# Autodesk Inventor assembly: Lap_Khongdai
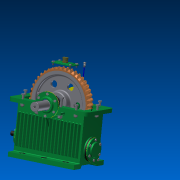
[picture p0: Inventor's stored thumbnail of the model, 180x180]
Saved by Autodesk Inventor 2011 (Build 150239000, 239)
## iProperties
Created: 2011-05
Part Number: Lap_Khongdai
Document SubType Name: Assembly
Designer: 904Chiaki
Author: 904Chiaki
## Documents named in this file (39)
- E:\2.FINISH\DOAN_CTM_final\Lap_Khongdai.iam
- E:\2.FINISH\DOAN_CTM_final\Thanhop.ipt
- E:\2.FINISH\DOAN_CTM_final\Bearing2_1.ipt
- E:\2.FINISH\DOAN_CTM_final\Bearing2_2.ipt
- E:\2.FINISH\DOAN_CTM_final\Bearing3.ipt
- E:\2.FINISH\DOAN_CTM_final\Naphop.ipt
- E:\2.FINISH\DOAN_CTM_final\Napquansat.ipt
- E:\2.FINISH\DOAN_CTM_final\Nutthonghoi.iam
- E:\2.FINISH\DOAN_CTM_final\Chotdinhvi.ipt
- E:\2.FINISH\DOAN_CTM_final\Bulongbich.ipt
- E:\2.FINISH\DOAN_CTM_final\Daiocbich.ipt
- E:\2.FINISH\DOAN_CTM_final\Vongdembich.ipt
- E:\2.FINISH\DOAN_CTM_final\BulongCanhO.ipt
- E:\2.FINISH\DOAN_CTM_final\Daioccanho.ipt
- E:\2.FINISH\DOAN_CTM_final\VongdemcanhO.ipt
- E:\2.FINISH\DOAN_CTM_final\Vitghepnapcuatham.ipt
- E:\2.FINISH\DOAN_CTM_final\VongChandau2.ipt
- E:\2.FINISH\DOAN_CTM_final\Shaft3.ipt
- E:\2.FINISH\DOAN_CTM_final\Onglot.ipt
- E:\2.FINISH\DOAN_CTM_final\VongChandau1.ipt
- E:\2.FINISH\DOAN_CTM_final\Lap1_codai\Design Accelerator\Key Connection2.iam
- E:\2.FINISH\DOAN_CTM_final\Lap1_codai\Design Accelerator\Key Connection3.iam
- E:\2.FINISH\DOAN_CTM_final\Trucvit.iam
- E:\2.FINISH\DOAN_CTM_final\Coclot1.ipt
- E:\2.FINISH\DOAN_CTM_final\Coclot2.ipt
- E:\2.FINISH\DOAN_CTM_final\NapO2.ipt
- E:\2.FINISH\DOAN_CTM_final\NapO2_2.ipt
- E:\2.FINISH\DOAN_CTM_final\Vongphot2.ipt
- E:\2.FINISH\DOAN_CTM_final\VongdemnapO2.ipt
- E:\2.FINISH\DOAN_CTM_final\NapO1.ipt
- E:\2.FINISH\DOAN_CTM_final\NapO1_2.ipt
- E:\2.FINISH\DOAN_CTM_final\VongdemNapO1.ipt
- E:\2.FINISH\DOAN_CTM_final\Vongphot1.ipt
- C:\Users\HTYCOON\Documents\Inventor\Content Center Files\R2011\en-US\DIN 910(1)\DIN 910 - M16 x 1.5.ipt
- E:\2.FINISH\DOAN_CTM_final\VitghepnapO.ipt
- E:\2.FINISH\DOAN_CTM_final\Quethamdau.ipt
- C:\Users\HTYCOON\Documents\Inventor\Content Center Files\R2011\en-US\ISO 4035(2)\ISO 4035 - M39ISO.ipt
- E:\2.FINISH\DOAN_CTM_final\Washer 18 GOST 11872-89.ipt
- E:\2.FINISH\DOAN_CTM_final\Banhvit.iam
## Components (95 placed, 37 different names)
1. Thanhop:1 — Mate:42, Flush:7, Mate:65, Mate:69, Mate:75, Mate:79, Mate:83, Mate:87, Mate:105, Mate:107, Mate:109, Mate:111, Mate:124, Angle:6, Mate:154, Mate:155, Angle:13, Angle:19, Angle:21, Angle:22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
2. DIN 628 - T1 7208B - 40 x 80 x 18:1 — Mate:179, Mate:180, Mate:182
3. ISO 355 3DB - 40 x 80 x 19.75:1 — Mate:250, Mate:251, Mate:254
4. ISO 355 3DB - 40 x 80 x 19.75:2 — Mate:248, Mate:249, Mate:251, Mate:252
5. ISO 355 2CE - 70 x 110 x 31:1 — Mate:126, Flush:12
6. ISO 355 2CE - 70 x 110 x 31:2 — Mate:123, Flush:13, Mate:128, Mate:130, Mate:260
7. Naphop:1 — Mate:42, Flush:7, Mate:45, Flush:8, Flush:9, Mate:50, Flush:10, Mate:51, Flush:11, Mate:52, Mate:53, Mate:54, Mate:55, Mate:56, Mate:57, Mate:58, Mate:59, Mate:60, Mate:61, Mate:62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
8. Napquansat:1 — Mate:43, Mate:44, Mate:45, Flush:8, Flush:9, Mate:112, Mate:113, Mate:114, Mate:115, Mate:116, Mate:117, Mate:118, Mate:119
9. Nutthonghoi:2 [sub-assembly] — Mate:43, Mate:44
10. ISO 2338 4 h8 x 55 - B:1 — Mate:51, Flush:11
11. ISO 2338 4 h8 x 55 - B:2 — Mate:50, Flush:10
12. ISO 4014 M14 x 70:1 — Mate:62, Mate:63, Mate:86
13. ISO 7417 M14:1 — Mate:66, Mate:67
14. ISO 7092 ST 14 - 140 HV:1 — Mate:64, Mate:65, Mate:67
15. ISO 4014 M14 x 70:2 — Mate:60, Mate:61, Mate:78
16. ISO 7417 M14:2 — Mate:70, Mate:71
17. ISO 7092 ST 14 - 140 HV:2 — Mate:68, Mate:69, Mate:71
18. ISO 4014 M14 x 70:3 — Mate:58, Mate:59, Mate:74
19. ISO 7417 M14:3 — Mate:72, Mate:73, Mate:74
20. ISO 7092 ST 14 - 140 HV:3 — Mate:72, Mate:73, Mate:75
21. ISO 4014 M14 x 70:4 — Mate:56, Mate:57, Mate:64, Mate:66
22. ISO 7417 M14:4 — Mate:76, Mate:77, Mate:78
23. ISO 7092 ST 14 - 140 HV:4 — Mate:76, Mate:77, Mate:79
24. ISO 4014 M14 x 70:5 — Mate:54, Mate:55, Mate:82
25. ISO 7417 M14:5 — Mate:80, Mate:81, Mate:82
26. ISO 7092 ST 14 - 140 HV:5 — Mate:80, Mate:81, Mate:83
27. ISO 4014 M14 x 70:6 — Mate:52, Mate:53, Mate:68, Mate:70
28. ISO 7417 M14:6 — Mate:84, Mate:85, Mate:86
29. ISO 7092 ST 14 - 140 HV:6 — Mate:84, Mate:85, Mate:87
30. ISO 4014 M16 x 120:1 — Mate:93, Mate:94, Mate:106
31. ISO 7414 M16:1 — Mate:96, Mate:97, Mate:104
32. ISO 7092 ST 16 - 140 HV:1 — Mate:96, Mate:97, Mate:105
33. ISO 4014 M16 x 120:2 — Mate:92, Mate:95, Mate:104
34. ISO 7414 M16:2 — Mate:98, Mate:99, Mate:106
35. ISO 7092 ST 16 - 140 HV:2 — Mate:98, Mate:99, Mate:107
36. ISO 4014 M16 x 120:3 — Mate:90, Mate:91, Mate:110
37. ISO 7414 M16:3 — Mate:100, Mate:101, Mate:108
38. ISO 7092 ST 16 - 140 HV:3 — Mate:100, Mate:101, Mate:109
39. ISO 4014 M16 x 120:4 — Mate:88, Mate:89, Mate:108
40. ISO 7414 M16:4 — Mate:102, Mate:103, Mate:110
41. ISO 7092 ST 16 - 140 HV:4 — Mate:102, Mate:103, Mate:111
42. ISO 4017 M10 x 20:1 — Mate:112, Mate:113
43. ISO 4017 M10 x 20:2 — Mate:114, Mate:117
44. ISO 4017 M10 x 20:3 — Mate:115, Mate:118
45. ISO 4017 M10 x 20:4 — Mate:116, Mate:119
46. VongChandau2:1 — Mate:127, Mate:129
47. VongChandau2:2 — Mate:123, Mate:130, Mate:131, Mate:133
48. Shaft:3 — Mate:124, Mate:126, Mate:127, Flush:12, Flush:13, Mate:128, Angle:6, Mate:129, Mate:131, Mate:132, Flush:14, Angle:11, Mate:140, Mate:157, Mate:158, Mate:161, Angle:25, Mate:257, Mate:259
49. Onglot:1 — Mate:132, Mate:133
50. VongChandau1:1 — Mate:181, Mate:182
51. VongChandau1:2 — Mate:183, Mate:252
52. Key Connection:1 [sub-assembly]
53. Key Connection:2 [sub-assembly] — Flush:14, Angle:11, Mate:140, Mate:258
54. Trucvit:1 [sub-assembly] — Mate:177, Mate:179, Mate:180, Mate:181, Mate:183, Mate:184, Mate:187, Mate:188, Angle:25, Mate:248, Mate:249, Mate:250, Mate:253, Angle:26, Mate:255
55. Coclot1:1 — Mate:184, Mate:185, Mate:186, Angle:23, Angle:24
56. Coclot2:1 — Mate:154, Mate:155, Angle:13, Mate:166, Mate:167, Mate:173
57. NapO2:1 — Mate:159, Angle:18, Mate:164, Mate:214, Mate:215, Mate:216, Mate:217, Mate:218, Mate:219, Mate:232, Mate:233, Mate:234, Mate:235, Mate:236, Mate:237
58. NapO2_2:1 — Mate:156, Tangent:1, Angle:15, Mate:165, Mate:202, Mate:203, Mate:204, Mate:205, Mate:206, Mate:207, Mate:244, Mate:245, Mate:260
59. Vongphot2:1 — Mate:156, Tangent:1, Mate:157
60. VongdemnapO2:1 — Mate:160, Mate:161, Angle:16, Mate:165
61. VongdemnapO2:2 — Mate:162, Mate:163, Angle:17, Mate:164
62. NapO1:1 — Mate:170, Tangent:2, Angle:21, Mate:188, Mate:189, Mate:208, Mate:209, Mate:210, Mate:211, Mate:212, Mate:213, Mate:238, Mate:239, Mate:240, Mate:241, Mate:242, Mate:243
63. NapO1_2:1 — Mate:173, Mate:174, Angle:22, Mate:220, Mate:221, Mate:222, Mate:223, Mate:224, Mate:225, Mate:226, Mate:227, Mate:228, Mate:229, Mate:230, Mate:231
64. VongdemNapO1:1 — Mate:186, Mate:187, Angle:24, Mate:189
65. Vongphot1:1 — Mate:170, Tangent:2
66. VongdemNapO1:2 — Mate:166, Mate:167, Angle:19, Mate:174
67. DIN 910 (Fine Thread) M16 x 1.5:1 — Mate:198, Mate:199
68. ISO 4017 M10 x 25:1 — Mate:220, Mate:230
69. ISO 4017 M10 x 25:2 — Mate:225, Mate:228
70. ISO 4017 M10 x 25:3 — Mate:224, Mate:227
71. ISO 4017 M10 x 25:4 — Mate:223, Mate:226
72. ISO 4017 M10 x 25:5 — Mate:222, Mate:229
73. ISO 4017 M10 x 25:6 — Mate:221, Mate:231
74. ISO 4017 M10 x 25:7 — Mate:214, Mate:236
75. ISO 4017 M10 x 25:8 — Mate:215, Mate:235
76. ISO 4017 M10 x 25:9 — Mate:216, Mate:234
77. ISO 4017 M10 x 25:10 — Mate:217, Mate:232
78. ISO 4017 M10 x 25:11 — Mate:218, Mate:233
79. ISO 4017 M10 x 25:12 — Mate:219, Mate:237
80. ISO 4017 M10 x 25:13 — Mate:208, Mate:242
81. ISO 4017 M10 x 25:14 — Mate:209, Mate:243
82. ISO 4017 M10 x 25:15 — Mate:210, Mate:238
83. ISO 4017 M10 x 25:16 — Mate:211, Mate:241
84. ISO 4017 M10 x 25:17 — Mate:212, Mate:240
85. ISO 4017 M10 x 25:18 — Mate:213, Mate:239
86. ISO 4017 M10 x 25:19 — Mate:202, Flush:19, Mate:245
87. ISO 4017 M10 x 25:20 — Mate:207, Flush:16, Flush:18
88. ISO 4017 M10 x 25:21 — Mate:206, Flush:16, Flush:17
89. ISO 4017 M10 x 25:22 — Mate:205, Flush:17
90. ISO 4017 M10 x 25:23 — Mate:204, Mate:244
91. ISO 4017 M10 x 25:24 — Mate:203, Flush:18, Flush:19
92. Quethamdau:1 — Mate:246, Mate:247
93. ISO 4035 M39:1 — Mate:255, Mate:256
94. Washer GOST 11872-89 18:1 — Mate:253, Mate:254, Angle:26, Mate:256
95. Banhvit:1 [sub-assembly] — Mate:257, Mate:258, Mate:259
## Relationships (203: Mate 175, Angle 14, Flush 12, Tangent 2)
- Mate:42: Thanhop:1 ↔ Naphop:1
- Flush:7: Thanhop:1 ↔ Naphop:1
- Mate:43: Napquansat:1 ↔ Nutthonghoi:2
- Mate:44: Napquansat:1 ↔ Nutthonghoi:2
- Mate:45: Naphop:1 ↔ Napquansat:1
- Flush:8: Naphop:1 ↔ Napquansat:1
- Flush:9: Naphop:1 ↔ Napquansat:1
- Mate:50: Naphop:1 ↔ ISO 2338 4 h8 x 55 - B:2
- Flush:10: Naphop:1 ↔ ISO 2338 4 h8 x 55 - B:2
- Mate:51: Naphop:1 ↔ ISO 2338 4 h8 x 55 - B:1
- Flush:11: Naphop:1 ↔ ISO 2338 4 h8 x 55 - B:1
- Mate:52: Naphop:1 ↔ ISO 4014 M14 x 70:6
- Mate:53: Naphop:1 ↔ ISO 4014 M14 x 70:6
- Mate:54: Naphop:1 ↔ ISO 4014 M14 x 70:5
- Mate:55: Naphop:1 ↔ ISO 4014 M14 x 70:5
- Mate:56: Naphop:1 ↔ ISO 4014 M14 x 70:4
- Mate:57: Naphop:1 ↔ ISO 4014 M14 x 70:4
- Mate:58: Naphop:1 ↔ ISO 4014 M14 x 70:3
- Mate:59: Naphop:1 ↔ ISO 4014 M14 x 70:3
- Mate:60: Naphop:1 ↔ ISO 4014 M14 x 70:2
- Mate:61: Naphop:1 ↔ ISO 4014 M14 x 70:2
- Mate:62: Naphop:1 ↔ ISO 4014 M14 x 70:1
- Mate:63: Naphop:1 ↔ ISO 4014 M14 x 70:1
- Mate:64: ISO 7092 ST 14 - 140 HV:1 ↔ ISO 4014 M14 x 70:4
- Mate:65: Thanhop:1 ↔ ISO 7092 ST 14 - 140 HV:1
- Mate:66: ISO 7417 M14:1 ↔ ISO 4014 M14 x 70:4
- Mate:67: ISO 7417 M14:1 ↔ ISO 7092 ST 14 - 140 HV:1
- Mate:68: ISO 7092 ST 14 - 140 HV:2 ↔ ISO 4014 M14 x 70:6
- Mate:69: Thanhop:1 ↔ ISO 7092 ST 14 - 140 HV:2
- Mate:70: ISO 7417 M14:2 ↔ ISO 4014 M14 x 70:6
- Mate:71: ISO 7417 M14:2 ↔ ISO 7092 ST 14 - 140 HV:2
- Mate:72: ISO 7417 M14:3 ↔ ISO 7092 ST 14 - 140 HV:3
- Mate:73: ISO 7417 M14:3 ↔ ISO 7092 ST 14 - 140 HV:3
- Mate:74: ISO 4014 M14 x 70:3 ↔ ISO 7417 M14:3
- Mate:75: Thanhop:1 ↔ ISO 7092 ST 14 - 140 HV:3
- Mate:76: ISO 7417 M14:4 ↔ ISO 7092 ST 14 - 140 HV:4
- Mate:77: ISO 7417 M14:4 ↔ ISO 7092 ST 14 - 140 HV:4
- Mate:78: ISO 4014 M14 x 70:2 ↔ ISO 7417 M14:4
- Mate:79: Thanhop:1 ↔ ISO 7092 ST 14 - 140 HV:4
- Mate:80: ISO 7417 M14:5 ↔ ISO 7092 ST 14 - 140 HV:5
- Mate:81: ISO 7417 M14:5 ↔ ISO 7092 ST 14 - 140 HV:5
- Mate:82: ISO 4014 M14 x 70:5 ↔ ISO 7417 M14:5
- Mate:83: Thanhop:1 ↔ ISO 7092 ST 14 - 140 HV:5
- Mate:84: ISO 7417 M14:6 ↔ ISO 7092 ST 14 - 140 HV:6
- Mate:85: ISO 7417 M14:6 ↔ ISO 7092 ST 14 - 140 HV:6
- Mate:86: ISO 4014 M14 x 70:1 ↔ ISO 7417 M14:6
- Mate:87: Thanhop:1 ↔ ISO 7092 ST 14 - 140 HV:6
- Mate:88: Naphop:1 ↔ ISO 4014 M16 x 120:4
- Mate:89: Naphop:1 ↔ ISO 4014 M16 x 120:4
- Mate:90: Naphop:1 ↔ ISO 4014 M16 x 120:3
- Mate:91: Naphop:1 ↔ ISO 4014 M16 x 120:3
- Mate:92: Naphop:1 ↔ ISO 4014 M16 x 120:2
- Mate:93: Naphop:1 ↔ ISO 4014 M16 x 120:1
- Mate:94: Naphop:1 ↔ ISO 4014 M16 x 120:1
- Mate:95: Naphop:1 ↔ ISO 4014 M16 x 120:2
- Mate:96: ISO 7414 M16:1 ↔ ISO 7092 ST 16 - 140 HV:1
- Mate:97: ISO 7414 M16:1 ↔ ISO 7092 ST 16 - 140 HV:1
- Mate:98: ISO 7414 M16:2 ↔ ISO 7092 ST 16 - 140 HV:2
- Mate:99: ISO 7414 M16:2 ↔ ISO 7092 ST 16 - 140 HV:2
- Mate:100: ISO 7414 M16:3 ↔ ISO 7092 ST 16 - 140 HV:3
- Mate:101: ISO 7414 M16:3 ↔ ISO 7092 ST 16 - 140 HV:3
- Mate:102: ISO 7414 M16:4 ↔ ISO 7092 ST 16 - 140 HV:4
- Mate:103: ISO 7414 M16:4 ↔ ISO 7092 ST 16 - 140 HV:4
- Mate:104: ISO 7414 M16:1 ↔ ISO 4014 M16 x 120:2
- Mate:105: Thanhop:1 ↔ ISO 7092 ST 16 - 140 HV:1
- Mate:106: ISO 4014 M16 x 120:1 ↔ ISO 7414 M16:2
- Mate:107: Thanhop:1 ↔ ISO 7092 ST 16 - 140 HV:2
- Mate:108: ISO 7414 M16:3 ↔ ISO 4014 M16 x 120:4
- Mate:109: Thanhop:1 ↔ ISO 7092 ST 16 - 140 HV:3
- Mate:110: ISO 4014 M16 x 120:3 ↔ ISO 7414 M16:4
- Mate:111: Thanhop:1 ↔ ISO 7092 ST 16 - 140 HV:4
- Mate:112: Napquansat:1 ↔ ISO 4017 M10 x 20:1
- Mate:113: Napquansat:1 ↔ ISO 4017 M10 x 20:1
- Mate:114: Napquansat:1 ↔ ISO 4017 M10 x 20:2
- Mate:115: Napquansat:1 ↔ ISO 4017 M10 x 20:3
- Mate:116: Napquansat:1 ↔ ISO 4017 M10 x 20:4
- Mate:117: Napquansat:1 ↔ ISO 4017 M10 x 20:2
- Mate:118: Napquansat:1 ↔ ISO 4017 M10 x 20:3
- Mate:119: Napquansat:1 ↔ ISO 4017 M10 x 20:4
- Mate:123: ISO 355 2CE - 70 x 110 x 31:2 ↔ VongChandau2:2
- Mate:124: Thanhop:1 ↔ Shaft:3
- Mate:126: ISO 355 2CE - 70 x 110 x 31:1 ↔ Shaft:3
- Mate:127: VongChandau2:1 ↔ Shaft:3
- Flush:12: ISO 355 2CE - 70 x 110 x 31:1 ↔ Shaft:3
- Flush:13: ISO 355 2CE - 70 x 110 x 31:2 ↔ Shaft:3
- Mate:128: ISO 355 2CE - 70 x 110 x 31:2 ↔ Shaft:3
- Angle:6: Thanhop:1 ↔ Shaft:3
- Mate:129: VongChandau2:1 ↔ Shaft:3
- Mate:130: ISO 355 2CE - 70 x 110 x 31:2 ↔ VongChandau2:2
- Mate:131: VongChandau2:2 ↔ Shaft:3
- Mate:132: Shaft:3 ↔ Onglot:1
- Mate:133: VongChandau2:2 ↔ Onglot:1
- Flush:14: Shaft:3 ↔ Key Connection:2
- Angle:11: Shaft:3 ↔ Key Connection:2
- Mate:140: Shaft:3 ↔ Key Connection:2
- Mate:154: Thanhop:1 ↔ Coclot2:1
- Mate:155: Thanhop:1 ↔ Coclot2:1
- Angle:13: Thanhop:1 ↔ Coclot2:1
- Mate:156: NapO2_2:1 ↔ Vongphot2:1
- Tangent:1: NapO2_2:1 ↔ Vongphot2:1
- Mate:157: Shaft:3 ↔ Vongphot2:1
- Mate:158: Naphop:1 ↔ Shaft:3
- Angle:15: Naphop:1 ↔ NapO2_2:1
- Mate:159: Naphop:1 ↔ NapO2:1
- Mate:160: Naphop:1 ↔ VongdemnapO2:1
- Mate:161: Shaft:3 ↔ VongdemnapO2:1
- Angle:16: Naphop:1 ↔ VongdemnapO2:1
- Mate:162: Naphop:1 ↔ VongdemnapO2:2
- Mate:163: Naphop:1 ↔ VongdemnapO2:2
- Angle:17: Naphop:1 ↔ VongdemnapO2:2
- Angle:18: Naphop:1 ↔ NapO2:1
- Mate:164: NapO2:1 ↔ VongdemnapO2:2
- Mate:165: NapO2_2:1 ↔ VongdemnapO2:1
- Mate:166: Coclot2:1 ↔ VongdemNapO1:2
- Mate:167: Coclot2:1 ↔ VongdemNapO1:2
- Angle:19: Thanhop:1 ↔ VongdemNapO1:2
- Mate:170: NapO1:1 ↔ Vongphot1:1
- Tangent:2: NapO1:1 ↔ Vongphot1:1
- Angle:21: Thanhop:1 ↔ NapO1:1
- Mate:173: Coclot2:1 ↔ NapO1_2:1
- Mate:174: NapO1_2:1 ↔ VongdemNapO1:2
- Angle:22: Thanhop:1 ↔ NapO1_2:1
- Mate:177: Thanhop:1 ↔ Trucvit:1
- Mate:179: DIN 628 - T1 7208B - 40 x 80 x 18:1 ↔ Trucvit:1
- Mate:180: DIN 628 - T1 7208B - 40 x 80 x 18:1 ↔ Trucvit:1
- Mate:181: VongChandau1:1 ↔ Trucvit:1
- Mate:182: DIN 628 - T1 7208B - 40 x 80 x 18:1 ↔ VongChandau1:1
- Mate:183: VongChandau1:2 ↔ Trucvit:1
- Mate:184: Trucvit:1 ↔ Coclot1:1
- Mate:185: Thanhop:1 ↔ Coclot1:1
- Mate:186: Coclot1:1 ↔ VongdemNapO1:1
- Mate:187: Trucvit:1 ↔ VongdemNapO1:1
- Angle:23: Thanhop:1 ↔ Coclot1:1
- Angle:24: Coclot1:1 ↔ VongdemNapO1:1
- Mate:188: Trucvit:1 ↔ NapO1:1
- Mate:189: NapO1:1 ↔ VongdemNapO1:1
- Angle:25: Shaft:3 ↔ Trucvit:1
- Mate:198: Thanhop:1 ↔ DIN 910 (Fine Thread) M16 x 1.5:1
- Mate:199: Thanhop:1 ↔ DIN 910 (Fine Thread) M16 x 1.5:1
- Mate:202: NapO2_2:1 ↔ ISO 4017 M10 x 25:19
- Mate:203: NapO2_2:1 ↔ ISO 4017 M10 x 25:24
- Mate:204: NapO2_2:1 ↔ ISO 4017 M10 x 25:23
- Mate:205: NapO2_2:1 ↔ ISO 4017 M10 x 25:22
- Mate:206: NapO2_2:1 ↔ ISO 4017 M10 x 25:21
- Mate:207: NapO2_2:1 ↔ ISO 4017 M10 x 25:20
- Mate:208: NapO1:1 ↔ ISO 4017 M10 x 25:13
- Mate:209: NapO1:1 ↔ ISO 4017 M10 x 25:14
- Mate:210: NapO1:1 ↔ ISO 4017 M10 x 25:15
- Mate:211: NapO1:1 ↔ ISO 4017 M10 x 25:16
- Mate:212: NapO1:1 ↔ ISO 4017 M10 x 25:17
- Mate:213: NapO1:1 ↔ ISO 4017 M10 x 25:18
- Mate:214: NapO2:1 ↔ ISO 4017 M10 x 25:7
- Mate:215: NapO2:1 ↔ ISO 4017 M10 x 25:8
- Mate:216: NapO2:1 ↔ ISO 4017 M10 x 25:9
- Mate:217: NapO2:1 ↔ ISO 4017 M10 x 25:10
- Mate:218: NapO2:1 ↔ ISO 4017 M10 x 25:11
- Mate:219: NapO2:1 ↔ ISO 4017 M10 x 25:12
- Mate:220: NapO1_2:1 ↔ ISO 4017 M10 x 25:1
- Mate:221: NapO1_2:1 ↔ ISO 4017 M10 x 25:6
- Mate:222: NapO1_2:1 ↔ ISO 4017 M10 x 25:5
- Mate:223: NapO1_2:1 ↔ ISO 4017 M10 x 25:4
- Mate:224: NapO1_2:1 ↔ ISO 4017 M10 x 25:3
- Mate:225: NapO1_2:1 ↔ ISO 4017 M10 x 25:2
- Mate:226: NapO1_2:1 ↔ ISO 4017 M10 x 25:4
- Mate:227: NapO1_2:1 ↔ ISO 4017 M10 x 25:3
- Mate:228: NapO1_2:1 ↔ ISO 4017 M10 x 25:2
- Mate:229: NapO1_2:1 ↔ ISO 4017 M10 x 25:5
- Mate:230: NapO1_2:1 ↔ ISO 4017 M10 x 25:1
- Mate:231: NapO1_2:1 ↔ ISO 4017 M10 x 25:6
- Mate:232: NapO2:1 ↔ ISO 4017 M10 x 25:10
- Mate:233: NapO2:1 ↔ ISO 4017 M10 x 25:11
- Mate:234: NapO2:1 ↔ ISO 4017 M10 x 25:9
- Mate:235: NapO2:1 ↔ ISO 4017 M10 x 25:8
- Mate:236: NapO2:1 ↔ ISO 4017 M10 x 25:7
- Mate:237: NapO2:1 ↔ ISO 4017 M10 x 25:12
- Mate:238: NapO1:1 ↔ ISO 4017 M10 x 25:15
- Mate:239: NapO1:1 ↔ ISO 4017 M10 x 25:18
- Mate:240: NapO1:1 ↔ ISO 4017 M10 x 25:17
- Mate:241: NapO1:1 ↔ ISO 4017 M10 x 25:16
- Mate:242: NapO1:1 ↔ ISO 4017 M10 x 25:13
- Mate:243: NapO1:1 ↔ ISO 4017 M10 x 25:14
- Mate:244: NapO2_2:1 ↔ ISO 4017 M10 x 25:23
- Flush:16: ISO 4017 M10 x 25:20 ↔ ISO 4017 M10 x 25:21
- Flush:17: ISO 4017 M10 x 25:21 ↔ ISO 4017 M10 x 25:22
- Flush:18: ISO 4017 M10 x 25:20 ↔ ISO 4017 M10 x 25:24
- Flush:19: ISO 4017 M10 x 25:19 ↔ ISO 4017 M10 x 25:24
- Mate:245: NapO2_2:1 ↔ ISO 4017 M10 x 25:19
- Mate:246: Naphop:1 ↔ Quethamdau:1
- Mate:247: Naphop:1 ↔ Quethamdau:1
- Mate:248: ISO 355 3DB - 40 x 80 x 19.75:2 ↔ Trucvit:1
- Mate:249: ISO 355 3DB - 40 x 80 x 19.75:2 ↔ Trucvit:1
- Mate:250: ISO 355 3DB - 40 x 80 x 19.75:1 ↔ Trucvit:1
- Mate:251: ISO 355 3DB - 40 x 80 x 19.75:1 ↔ ISO 355 3DB - 40 x 80 x 19.75:2
- Mate:252: ISO 355 3DB - 40 x 80 x 19.75:2 ↔ VongChandau1:2
- Mate:253: Trucvit:1 ↔ Washer GOST 11872-89 18:1
- Mate:254: ISO 355 3DB - 40 x 80 x 19.75:1 ↔ Washer GOST 11872-89 18:1
- Angle:26: Trucvit:1 ↔ Washer GOST 11872-89 18:1
- Mate:255: Trucvit:1 ↔ ISO 4035 M39:1
- Mate:256: ISO 4035 M39:1 ↔ Washer GOST 11872-89 18:1
- Mate:257: Shaft:3 ↔ Banhvit:1
- Mate:258: Key Connection:2 ↔ Banhvit:1
- Mate:259: Shaft:3 ↔ Banhvit:1
- Mate:260: ISO 355 2CE - 70 x 110 x 31:2 ↔ NapO2_2:1
